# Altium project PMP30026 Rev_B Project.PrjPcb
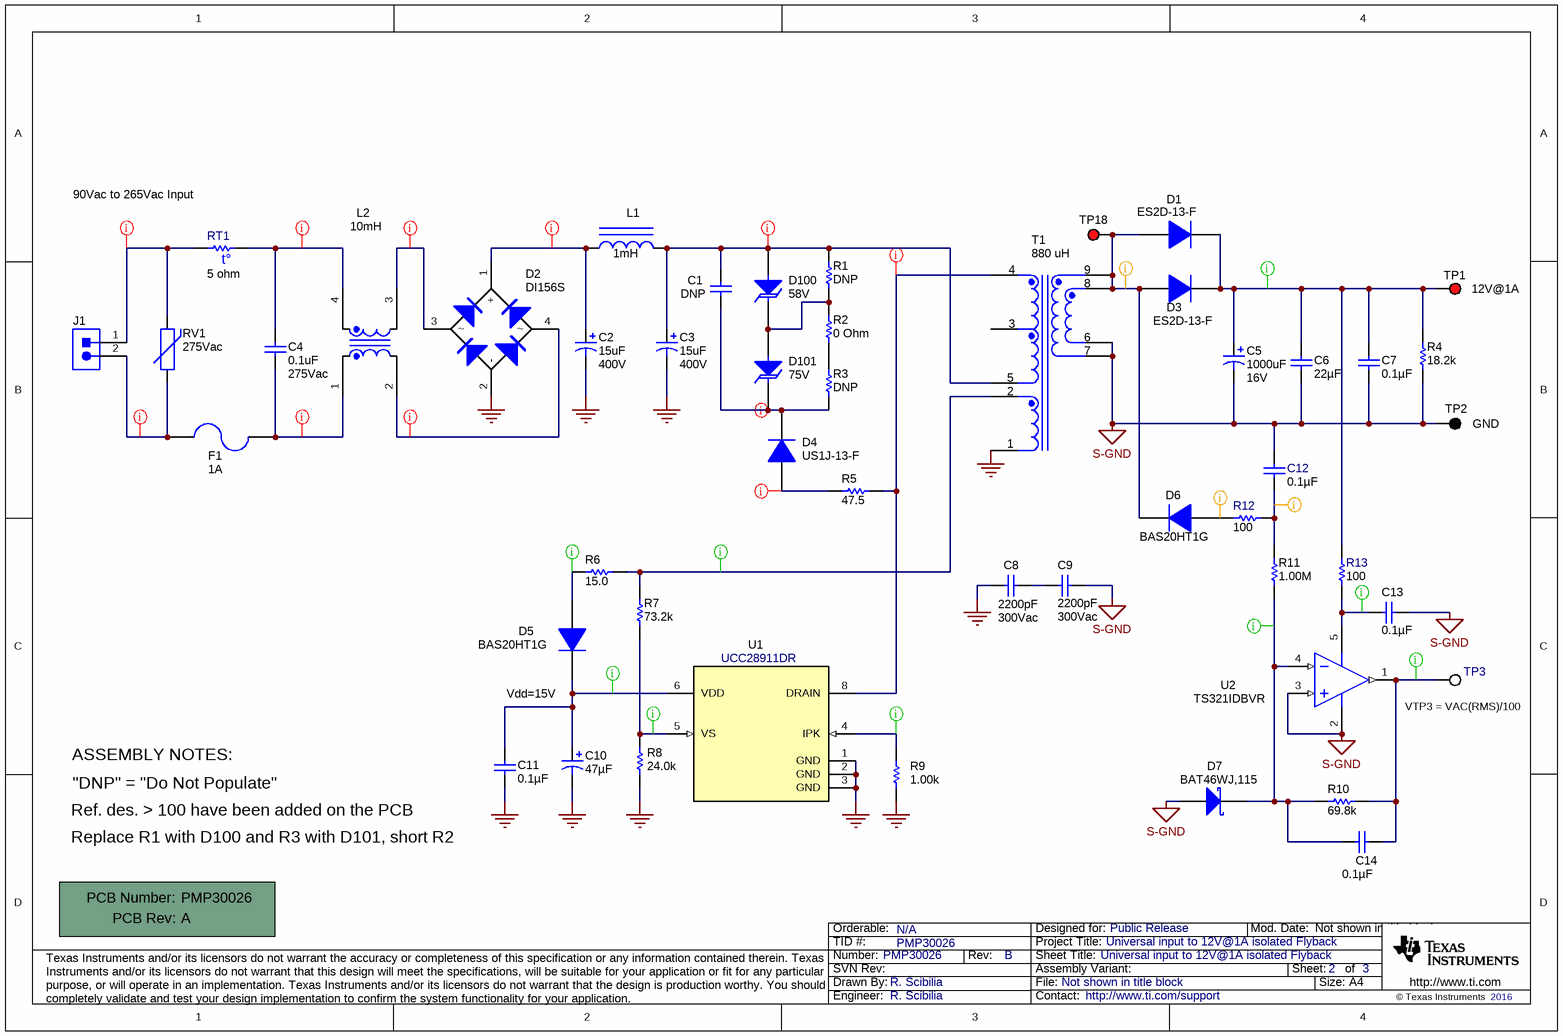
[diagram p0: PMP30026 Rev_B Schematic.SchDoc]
CopyrightYear: 2016; EVM_Orderable: N/A; PCB_Layout: R. Scibilia; PCB_Rev: A; PRJ_Customer: Public Release; PRJ_Engineer: R. Scibilia; PRJ_Number: PMP30026; PRJ_Title: Universal input to 12V@1A isolated Flyback; SCH_Rev: B; TechSupport: http://www.ti.com/support; TID: PMP30026
1 sheet, 50 parts. Net scope: global (net labels, ports and power ports of the same name join across sheets).
Board file: PMP30026 Rev_A.PcbDoc

## Sheet PMP30026 Rev_B Schematic.SchDoc: Universal input to 12V@1A isolated Flyback
size A4; Date: Not shown in title block; ApprovedBy: Not shown in title block; CheckedBy: Not shown in title block; Author: Not shown in title block; CompanyName: Not shown in title block; DrawnBy: R. Scibilia; Engineer: Not shown in title block; Organization: Not shown in title block; Address1: Not shown in title block; Address2: Not shown in title block; Address3: Not shown in title block; Address4: Not shown in title block; DocumentNumber: 1; Revision: Use project parameter SCH_Rev; SheetNumber: 2; SheetTotal: 3; PageSetup: Record=PageOptions¦CenterHorizontal=True¦CenterVertical=True¦PrintScale=1.00¦XCorrection=1.00¦YCorrection=1.00¦PrintKind=0¦BorderSize=5000000¦LeftOffset=0¦BottomOffset=0¦Orientation=2¦PaperLength=1000¦PaperWidth=1000¦Scale=100¦PaperSource=15¦PrintQuality=600¦MediaType=1¦DitherType=10¦PaperKind=Letter¦PrintScaleMode=1

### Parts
!PCB1  Printed Circuit Board  (value not drawn)  (mechanical)
C1  DNP  [1206]
C2  value 15uF  Value2: 400V  [EE_1000x2000]  (hidden comment: UVC2G150MPD)
C3  value 15uF  Value2: 400V  [EE_1000x2000]  (hidden comment: UVC2G150MPD)
C4  value 0.1uF  Value1: 275Vac  [R46_1300x1200x600]  (hidden comment: R46KF310000P1M)
C5  value 1000uF  Value2: 16V  [CAPPR5-10x16]  (hidden comment: 16ZLJ1000MCE10X16)
C6  ValueDisplayed: 22µF  [0805_HV]  (hidden comment: GRM21BR61E226ME44L)
C7  ValueDisplayed: 0.1µF  [0603]  (hidden comment: C1608X7R1H104K)
C8  value 2200pF  Value2: 300Vac  [PHE850_1300x400x900]  (hidden comment: R413F12200000M)
C9  value 2200pF  Value2: 300Vac  [PHE850_1300x400x900]  (hidden comment: R413F12200000M)
C10  ValueDisplayed: 47µF  [FM_500x1100]  (hidden comment: EEU-FM1E470)
C11  ValueDisplayed: 0.1µF  [0603]  (hidden comment: C1608X7R1H104K)
C12  ValueDisplayed: 0.1µF  [0603]  (hidden comment: GRM188R72A104KA35D)
C13  ValueDisplayed: 0.1µF  [0603]  (hidden comment: C1608X7R1H104K)
C14  ValueDisplayed: 0.1µF  [0603]  (hidden comment: C1608X7R1H104K)
D1  ES2D-13-F  [SMB]
D2  DI156S  [DF-S]
D3  ES2D-13-F  [SMB]
D4  US1J-13-F  [SMA]
D5  BAS20HT1G  [sod-323]
D6  BAS20HT1G  [sod-323]
D7  BAT46WJ,115  [SOD-323F]
D100  value 58V  [SMA]  (hidden comment: SMAJ58A)
D101  value 75V  [SMA]  (hidden comment: SMAJ75A)
F1  value 1A  [Fuse_RST]  (hidden comment: RST 1-BULK)
J1  CIM029P5  [PHOENIX_1757242]  (value not drawn)
L1  ValueDisplayed: 1mH  [WE-TI_5075]  (hidden comment: 7447462102)
L2  ValueDisplayed: 10mH  [WE-CMB_XS]  (hidden comment: 744821110)
R1  DNP  [1206]
R2  0 Ohm  [1206]
R3  DNP  [1206]
R4  ValueDisplayed: 18.2k  [0603]  (hidden comment: CRCW060318K2FKEA)
R5  ValueDisplayed: 47.5  [0805_HV]  (hidden comment: CRCW080547R5FKEA)
R6  value 15.0  [0603]  (hidden comment: CRCW060315R0FKEA)
R7  ValueDisplayed: 73.2k  [0603]  (hidden comment: CRCW060373K2FKEA)
R8  ValueDisplayed: 24.0k  [0603]  (hidden comment: RC0603FR-0724KL)
R9  ValueDisplayed: 1.00k  [0603]  (hidden comment: CRCW06031K00FKEA)
R10  ValueDisplayed: 69.8k  [0603]  (hidden comment: CRCW060369K8FKEA)
R11  ValueDisplayed: 1.00M  [0603]  (hidden comment: CRCW06031M00FKEA)
R12  ValueDisplayed: 100  [0603]  (hidden comment: CRCW0603100RFKEA)
R13  ValueDisplayed: 100  [0603]  (hidden comment: CRCW0603100RFKEA)
RT1  value 5 ohm  [MF72D5]  (hidden comment: MF72-005D5)
RV1  value 275Vac  [TDK_B72214S2211K101]  (hidden comment: B72214S271K101)
T1  value 880 uH  [WURTH_7508110166]  (hidden comment: 37694404)
TP1  5000  [Keystone5000]  (value not drawn)
TP2  5001  [Keystone5001]  (value not drawn)
TP3  5002  [Keystone5002]  (value not drawn)
TP18  5000  [Keystone5000]  (value not drawn)
U1  UCC28911DR  [D0007A_N]
U2  TS321IDBVR  [DBV0005A_N]

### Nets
GND: C2.2(-) C3.2(-) C8.2 C10.2(-) C11.2 D2.2(-) R8.1 R9.1 T1.4 U1.1(GND) U1.2(GND) U1.3(GND)
S-GND: C5.2(-) C6.2 C7.2 C9.1 C12.1 C13.2 D7.2(A) R4.1 T1.8 T1.9 TP2.1 U2.2(VCC-) U2.3(IN+)
NetC1_1: C1.1 C3.1(+) D100.2(A) L1.2 R1.2 T1.1
NetC1_2: C1.2 D4.1(K) D101.1(K) R3.2
NetC2_1: C2.1(+) D2.1(+) L1.1
NetC4_1: C4.1 F1.2 L2.1
NetC4_2: C4.2 L2.4 RT1.2
NetC5_1: C5.1(+) C6.1 C7.1 D1.1(K) D3.1(K) R4.2 R13.2 TP1.1
NetC8_1: C8.1 C9.2
NetC10_1: C10.1(+) C11.1 D5.1(K) U1.6(VDD)
NetC12_2: C12.2 R11.2 R12.2
NetC13_1: C13.1 R13.1 U2.5(VCC+)
NetC14_1: C14.1 D7.1(K) R10.1 R11.1 U2.4(IN-)
NetC14_2: C14.2 R10.2 TP3.1 U2.1(OUT)
NetD1_2: D1.2(A) D3.2(A) D6.1(K) T1.6 T1.7 TP18.1
NetD2_3: D2.3 L2.3
NetD2_4: D2.4 L2.2
NetD4_2: D4.2(A) R5.2
NetD5_2: D5.2(A) R6.2
NetD6_2: D6.2(A) R12.1
NetD100_1: D100.1(K) D101.2(A) R1.1 R2.2
NetF1_1: F1.1 J1.2 RV1.1
NetJ1_1: J1.1 RT1.1 RV1.2
NetR2_1: R2.1 R3.1
NetR5_1: R5.1 T1.3 U1.8(DRAIN)
NetR6_1: R6.1 R7.2 T1.5
NetR7_1: R7.1 R8.2 U1.5(VS)
NetR9_2: R9.2 U1.4(IPK)

Not connected (* = marked no-connect by the designer): T1 2

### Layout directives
rule Clearance Constraint [Clearance = 30mil]: NetC1_1, NetC1_2, NetC2_1, NetC4_1, NetC4_2, NetD2_3, NetD2_4, NetD4_2, NetF1_1, NetJ1_1, NetR5_1
rule Clearance Constraint [Clearance = 10mil]: NetC5_1, NetC10_1, NetC13_1, NetC14_1, NetC14_2, NetD5_2, NetR6_1, NetR7_1, NetR9_2
rule Clearance Constraint [Clearance = 15mil]: NetC12_2, NetD1_2, NetD6_2

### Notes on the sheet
- (near RT1) 90Vac to 265Vac Input
- (near T1) 4
- (near T1) 9
- (near T1) 8
- (near TP1) 12V@1A
- (near T1) 5
- (near T1) 3
- (near T1) 6
- (near T1) 7
- (near T1) 2
- (near T1) 1
- (near TP2) GND
- Vdd=15V
- (near TP3) VTP3 = VAC(RMS)/100
- ASSEMBLY NOTES:
- "DNP" = "Do Not Populate"
- Ref. des. > 100 have been added on the PCB
- Replace R1 with D100 and R3 with D101, short R2

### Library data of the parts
!PCB1 = PCB: Manufacturer: Any; PartNumber: PMP30026; SymbolCreator: a0412235
C1 = C3216X7R2J472K: Manufacturer: TDK; Polarized: N; CompType: Capacitor; U/M: EA; Cap_F: 0.0000000047; Tolerance_%: 10; ESR_ohm: 0.0962; TempCo: X7R; TaMin_C: -55; TaMax_C: 125; AEC Category: Q200
C2 C3 = EEU-EE2E220: CAP, AL, 15 µF, 400 V, +/- 20%, TH; Manufacturer: Nichicon; Polarized: Y; CompType: Capacitor; ValueDisplayed: 15µF; U/M: EA; Cap_F: 0.000022; Tolerance_%: 20; Value1: Unknown; VDC_V: 400; IRMS_A: 0.225; TaMin_C: -25; TaMax_C: 105; Cap_Case: 10x17.5mm; AEC Category: Q200
C4 = R46KF310050P0K: CAP, Film, 0.1 µF, 275 Vac, +/- 20%, TH; Manufacturer: Kemet; Polarized: N; CompType: Capacitor; ValueDisplayed: 0.1µF; U/M: EA; Cap_F: 0.0000001; Tolerance_%: 10; VDC_V: 560; Value2: 560V; TaMin_C: -40; TaMax_C: 110; Cap_Case: 13x11x5; AEC Category: Q200
C5 = 16ZLJ1000MCE10X16: CAP, AL, 1000 µF, 16 V, +/- 20%, TH; Manufacturer: Rubycon; Polarized: Y; CompType: Capacitor; ValueDisplayed: 1000µF; U/M: EA; Cap_F: 0.001; Tolerance_%: 20; Value1: Unknown; VDC_V: 16; TaMin_C: -40; TaMax_C: 105; Cap_Case: 10x16; AEC Category: Q200; AEC Qualified: N
C6 = GRM21BR61E226ME44L: CAP, CERM, 22 µF, 25 V, +/- 20%, X5R, 0805; Manufacturer: MuRata; Polarized: N; CompType: Capacitor; Value: 22uF; U/M: EA; Cap_F: 0.000022; Tolerance_%: 20; Value1: Unknown; VDC_V: 25; Value2: 25V; TaMin_C: -55; TaMax_C: 85; Cap_Case: 0805; AEC Category: Q200
C7 C11 C13 C14 = C1608X7R1H104K: CAP, CERM, 0.1 µF, 50 V, +/- 10%, X7R, 0603; Manufacturer: TDK; Polarized: N; CompType: Capacitor; Value: 0.1uF; U/M: EA; Cap_F: 0.0000001; Tolerance_%: 10; ESR_ohm: 0.017; Value1: 0.017 ohm; VDC_V: 50; Value2: 50V; TaMin_C: -55; TaMax_C: 125; AEC Category: Q200
C8 C9 = PHE850EA4220MA01R17: CAP, Film, 2200 pF, 300 VAC, Class Y2, R41 +/- 20%, TH; Manufacturer: Kemet; Polarized: N; CompType: Capacitor; U/M: EA; Cap_F: 0.0000000022; Tolerance_%: 20; Value1: Unknown; VDC_V: 300; TaMin_C: -55; TaMax_C: 110; Cap_Case: 13x4x9mm; AEC Category: Q200
C10 = EEU-FM1E470: CAP, AL, 47 µF, 25 V, +/- 20%, 0.3 ohm, TH; Manufacturer: Panasonic; Polarized: Y; CompType: Capacitor; Value: 47uF; U/M: EA; Cap_F: 0.000047; Tolerance_%: 20; Value1: 0.3 ohm; VDC_V: 25; Value2: 25V; ESR_ohm: 0.3; IRMS_A: 0.28; TaMin_C: -40; TaMax_C: 105; Cap_Case: 5x11; AEC Category: Q200; AEC Qualified: N
C12 = GRM188R72A104KA35D: CAP, CERM, 0.1 µF, 100 V, +/- 10%, X7R, 0603; Manufacturer: MuRata; Polarized: N; CompType: Capacitor; Value: 0.1uF; U/M: EA; Cap_F: 0.0000001; Tolerance_%: 10; Value1: Unknown; VDC_V: 100; Value2: 100V; TaMin_C: -55; TaMax_C: 125; AEC Category: Q200
D1 D3 = ES2D-13-F: Diode, Ultrafast, 200 V, 2 A, SMB; Manufacturer: Diodes Inc.; U/M: EA; Vf_V: 0.92; Value1: 2A; Value2: 0.92V; Io_A: 2; Vr_V: 200; TJmax_C: 150; RJC_CperW: 20; AEC Category: Q101
D2 = DF08SA: Diode, Bridge, 600 V, 1.5 A; Manufacturer: Panjit; U/M: EA; Vf_V: 1.1; Value1: 1.5A; Value2: 1.1V; Io_A: 1; Vr_V: 600; TJmax_C: 150; RJC_CperW: 15; Type: Switching-Bridge; AEC Category: Q101
D4 = US1J-13-F: Diode, Ultrafast, 600 V, 1 A, SMA; Manufacturer: Diodes Inc.; U/M: EA; Vf_V: 1.7; Value1: 1A; Value2: 1.7V; Io_A: 1; Vr_V: 600; TJmax_C: 150; AEC Category: Q101
D5 D6 = BAS316,115: DIODE SWITCH 200V 200MA SOD323; Manufacturer: ON Semiconductor; U/M: EA; Vf_V: 1.4; Value1: 0.25A; Vr_V: 100; Value2: 100V; TJmax_C: 150; Type: Ultrafast
D7 = BAT46WJ,115: Diode, Schottky, 100 V, 0.25 A, SOD-323F; Manufacturer: NXP Semiconductor; U/M: EA; Vf_V: 0.85; Value1: 0.25A; Value2: 0.85V; Io_A: 0.25; Vr_V: 100; TJmax_C: 150; AEC Category: Q101
D100 D101 = SMAJ58A: Diode, TVS, Uni, 58 V, 400 W, SMA; Manufacturer: Diodes Inc.; U/M: EA; Power_W: 400; Vr_V: 58; Value1: 400W; AEC Category: Q101
F1 = RST 500: FUSE BOARD MOUNT 1A 250VAC RAD; Manufacturer: Bel Fuse; U/M: EA; OpeningTime_100%_min: 1; OpeningTime_200%_max: 120; VDC_V: 250; VAC_V: 250V; Rtyp_Ohm: 0.18; MeltingTyp: 1.7; Vdrop: 0.114; Soldering_Wave_MaxTemp_C: 260; Soldering_Wave_MaxTime_s: 10
J1 = 1757242: Header (Shrouded), 5.08 mm, 2x1, Tin, R/A, TH; Manufacturer: CIM; SymbolCreator: a0412235
L1 = 7447462102: Inductor, Unshielded Drum Core, Ferrite, 1 mH, 0.25 A, 4.38 ohm, TH; Manufacturer: Wurth Elektronik; Value: 1mH; Ind_H: 1.0E-3; Imax_A: 0.25; Irms: 0.25A @ 40C rise; Isat: 0.27A @ 10% inductance drop; DCR_ohm: 4.38; Value2: 0.25A; AEC Category: Q200
L2 = 744821110: Coupled inductor, 10 mH, 0.7 A, 0.35 ohm, TH; Manufacturer: Wurth Elektronik; SymbolCreator: a0412235; Value: 10mH; Ind_H: 10.0E-3; DCR_ohm: 0.35
R1-R3 = CRCW120647K0JNEA: Manufacturer: Vishay-Dale; CompType: Resistor; Value: 47k; Res_ohm: 47000; Value_Code: 47k0; Tolerance_%: 5; Value1: 5%; Power_W: 0.25; Value2: 0.25W; VDC_V: 200; TempCo: 200 ppm/C; EIA_Code: E24; U/M: EA; AEC Category: Q200
R4 = CRCW060318K2FKEA: RES, 18.2 k, 1%, 0.1 W, 0603; Manufacturer: Vishay-Dale; CompType: Resistor; Value: 18.2k; Res_ohm: 18200; Value_Code: 18k2; Tolerance_%: 1; Power_W: 0.1; Value2: 0.1W; VDC_V: 75; TempCo: 100 ppm/C; EIA_Code: E96; U/M: EA; AEC Category: Q200
R5 = CRCW080547R5FKEA: RES, 47.5, 1%, 0.125 W, 0805; Manufacturer: Vishay-Dale; CompType: Resistor; Value: 47.5; Value_Code: 47R5; Tolerance_%: 1; Power_W: 0.125; Value2: 0.125W; VDC_V: 150; TempCo: 100 ppm/C; EIA_Code: E96; U/M: EA; AEC Category: Q200
R6 = CRCW060315R0FKEA: RES, 15.0 ohm, 1%, 0.1W, 0603; Manufacturer: Vishay-Dale; CompType: Resistor; Res_ohm: 15; Value_Code: 15R0; Tolerance_%: 1; Power_W: 0.1; VDC_V: 75; TempCo: 100 ppm/C; EIA_Code: E96; U/M: EA
R7 = CRCW060373K2FKEA: RES, 73.2 k, 1%, 0.1 W, 0603; Manufacturer: Vishay-Dale; CompType: Resistor; Value: 73.2k; Res_ohm: 73200; Value_Code: 73k2; Tolerance_%: 1; Power_W: 0.1; Value2: 0.1W; VDC_V: 75; TempCo: 100 ppm/C; EIA_Code: E96; U/M: EA; AEC Category: Q200
R8 = RC0603FR-0724KL: RES, 24.0 k, 1%, 0.1 W, 0603; Manufacturer: Yageo America; CompType: Resistor; Value: 24.0k; Res_ohm: 24000; Value_Code: 24k0; Tolerance_%: 1; Power_W: 0.1; Value2: 0.1W; VDC_V: 150; TempCo: 200 ppm/C; U/M: EA; AEC Category: Q200
R9 = CRCW06031K00FKEA: RES, 1.00 k, 1%, 0.1 W, 0603; Manufacturer: Vishay-Dale; CompType: Resistor; Value: 1.00k; Res_ohm: 1000; Value_Code: 1k00; Tolerance_%: 1; Power_W: 0.1; Value2: 0.1W; VDC_V: 75; TempCo: 100 ppm/C; EIA_Code: E96; U/M: EA; AEC Category: Q200
R10 = CRCW060369K8FKEA: RES, 69.8 k, 1%, 0.1 W, 0603; Manufacturer: Vishay-Dale; CompType: Resistor; Value: 69.8k; Res_ohm: 69800; Value_Code: 69k8; Tolerance_%: 1; Power_W: 0.1; Value2: 0.1W; VDC_V: 75; TempCo: 100 ppm/C; EIA_Code: E96; U/M: EA; AEC Category: Q200
R11 = CRCW06031M00FKEA: RES, 1.00 M, 1%, 0.1 W, 0603; Manufacturer: Vishay-Dale; CompType: Resistor; Value: 1.00Meg; Res_ohm: 1000000; Value_Code: 1M00; Tolerance_%: 1; Power_W: 0.1; Value2: 0.1W; VDC_V: 75; TempCo: 100 ppm/C; EIA_Code: E96; U/M: EA; AEC Category: Q200
R12 R13 = CRCW0603100RFKEA: RES, 100, 1%, 0.1 W, 0603; Manufacturer: Vishay-Dale; CompType: Resistor; Value: 100; Value_Code: 100R; Tolerance_%: 1; Power_W: 0.1; Value2: 0.1W; VDC_V: 75; TempCo: 100 ppm/C; EIA_Code: E96; U/M: EA; AEC Category: Q200
RT1 = MF72-005D5: Thermistor NTC, 5 ohm, 20%, MF72D5 TH; Manufacturer: Cantherm; Tolerance_%: 20; TaMin_C: -55; TaMax_C: 200; U/M: EA
RV1 = B72214S2211K101: VARISTOR 275Vac 6KA DISC 14MM; Manufacturer: TDK; SymbolCreator: a0412235
T1 = 7508110166: Transformer, 880 uH, TH; Manufacturer: PMA; SymbolCreator: Altium; U/M: EA
TP1 TP18 = 5000: Test Point, Miniature, Red, TH; Manufacturer: Keystone; CompType: Test Point Loop; U/M: EA
TP2 = 5001: Test Point, Miniature, Black, TH; Manufacturer: Keystone; CompType: Test Point Loop; U/M: EA
TP3 = 5002: Test Point, Miniature, White, TH; Manufacturer: Keystone; CompType: Test Point Loop; U/M: EA
U1 = UCC28911DR: High Voltage Flyback Switcher with Primary-side Regulation and Constant-Current Control, D0007A; Manufacturer: Texas Instruments; SymbolCreator: a0412235; CompType: IC; U/M: EA
U2 = TS321IDBVR: Low-Power Single Operational Amplifier, 3 to 30 V, -40 to 125 degC, 5-pin SOT23 (DBV0005A), Green (RoHS & no Sb/Br); Alternate Manufacturer: Texas Instruments; Alternate PartNumber: Equivalent; CMRR(Min)(dB): 65; GBW(Typ)(MHz): 0.8; IIB(Max)(pA): 200000; Iq per channel(Max)(mA): 1; Slew Rate(Typ)(V/us): 0.4; Sub Family: General Purpose Amplifier, High Supply Voltage Amplifier (>=30V); Total Supply Voltage(Max)(+5V is 5, +/-5V is 10): 30; Total Supply Voltage(Min)(+5V is 5, +/-5V is 10): 3; Vio (25C)(Max)(mV): 4; Vn at 1kHz(Typ)(nV/rtHz): 50

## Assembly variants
001: not fitted C10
